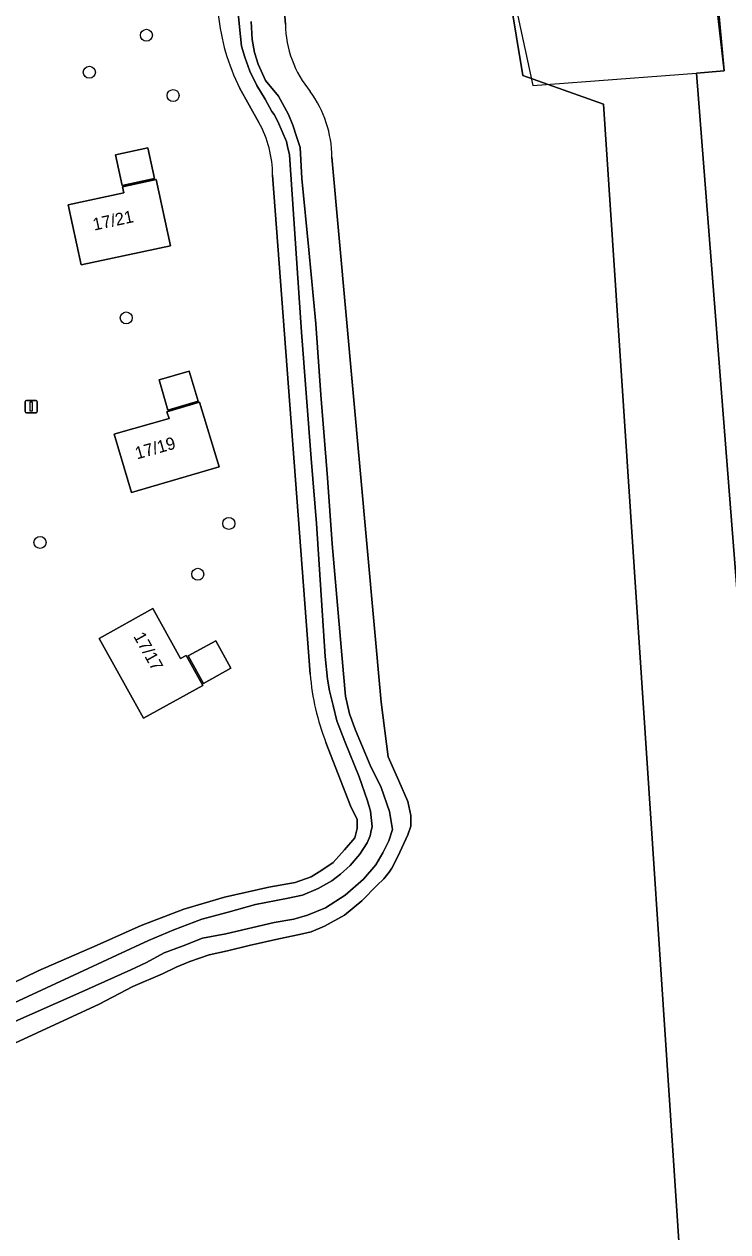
# Model space of a CAD drawing. Extents: x 157793 to 159380, y 380877 to 382313.
# Drawn here: x 157999.2 to 158056.4, y 381071.7 to 381170.1 of the extents above; entities that cross this region are included whole.
import ezdxf

# ---------------------------------------------------------------- set-up
doc = ezdxf.new("R2010")
doc.units = 0
for name, color, linetype in [('IMGEO_Boom', 7, 'Continuous'), ('IMGEO_Erf', 7, 'Continuous'), ('IMGEO_Groenvoorziening', 7, 'Continuous'), ('IMGEO_Hek', 7, 'Continuous'), ('IMGEO_Lichtmast', 7, 'Continuous'), ('IMGEO_Oever', 7, 'Continuous'), ('IMGEO_Pand', 7, 'Continuous'), ('IMGEO_Pand_nummerreeks', 7, 'Continuous'), ('IMGEO_Waterloop', 7, 'Continuous')]:
    doc.layers.add(name, color=color, linetype=linetype)

msp = doc.modelspace()

# ---------------------------------------------------------------- linework, layer by layer
at = {"layer": 'IMGEO_Boom'}
for centre in [(158009.132, 381169.157), (158004.492, 381166.14), (158011.308, 381164.25), (158007.497, 381146.143), (158015.843, 381129.408), (158000.478, 381127.86), (158013.314, 381125.266)]:
    msp.add_circle(centre, 0.489, dxfattribs=at)
at = {"layer": 'IMGEO_Erf'}
msp.add_lwpolyline([(158099.611, 381217.247), (158052.783, 381213.5), (158050.314, 381213.946), (158050.517, 381211.312), (158052.682, 381183.227), (158054.909, 381179.836), (158056.161, 381166.26), (158053.899, 381166.074), (158054.334, 381160.498), (158058.211, 381110.918)], dxfattribs=at)
at = {"layer": 'IMGEO_Groenvoorziening'}
for points in [[(158058.211, 381110.918), (158054.334, 381160.498), (158053.899, 381166.074), (158056.161, 381166.26), (158054.909, 381179.836), (158052.682, 381183.227), (158050.517, 381211.312), (158039.034, 381210.37), (158038.773, 381213.455), (158034.585, 381213.111), (158034.869, 381210.038), (158027.452, 381209.42), (158028.11, 381199.967), (158024.833, 381197.293), (158036.947, 381181.933), (158037.709, 381178.388), (158039.767, 381165.888), (158046.317, 381163.549), (158054.886, 381034.528), (158055.954, 381019.408), (158065.175, 380995.891)], [(158065.175, 380995.891), (158055.954, 381019.408), (158054.886, 381034.528), (158046.317, 381163.549), (158039.767, 381165.888), (158037.709, 381178.388), (158035.215, 381178.178), (158019.881, 381197.791), (158019.23, 381206.041), (158018.738, 381212.267), (158021.715, 381212.507), (158027.429, 381212.967)], [(158017.804, 381200.746), (158020.445, 381170.062)], [(157956.666, 381171.336), (157958.091, 381157.039), (157961.056, 381135.277), (157963.956, 381120.521), (157969.049, 381101.066), (157973.397, 381089.261), (157976.609, 381081.434), (158000.338, 381092.983), (158005.131, 381095.063), (158008.705, 381096.66), (158012.185, 381098.006), (158015.477, 381098.987), (158019.105, 381099.794), (158021.236, 381100.178), (158022.534, 381100.639), (158023.403, 381101.169), (158024.341, 381101.792), (158025.261, 381102.828), (158026.085, 381103.81), (158026.273, 381104.572), (158026.275, 381105.306), (158025.756, 381106.409), (158023.749, 381111.568)], [(158018.292, 381162.055), (158016.704, 381164.87)], [(158024.231, 381159.232), (158028.249, 381114.861), (158028.806, 381110.404), (158029.674, 381108.44), (158030.403, 381106.775), (158030.639, 381105.62), (158030.643, 381104.766), (158030.421, 381104.052), (158029.594, 381102.283), (158029.108, 381101.352), (158028.892, 381101.006), (158028.454, 381100.469), (158027.892, 381099.936), (158026.659, 381098.685), (158025.243, 381097.513), (158023.638, 381096.615), (158022.532, 381096.165), (158021.595, 381095.941), (158019.914, 381095.598), (158017.495, 381095.035), (158015.721, 381094.598), (158014.249, 381094.288), (158012.671, 381093.747), (158011.557, 381093.285), (158010.452, 381092.749), (158008.04, 381091.694), (158005.302, 381090.26), (157978.213, 381077.766)], [(158022.465, 381117.132), (158019.404, 381157.762)]]:
    msp.add_lwpolyline(points, dxfattribs=at)
for points in [[(158006.631, 381159.434), (158009.248, 381160.002), (158009.784, 381157.493), (158007.175, 381156.927)], [(158007.31, 381156.325), (158007.199, 381156.817), (158009.94, 381157.412), (158011.096, 381152.014), (158003.83, 381150.459), (158002.782, 381155.356)], [(158012.62, 381141.82), (158013.343, 381139.359), (158010.885, 381138.643), (158010.164, 381141.099)], [(158010.979, 381137.949), (158010.808, 381138.501), (158013.46, 381139.28), (158015.052, 381134.022), (158007.924, 381131.927), (158006.524, 381136.689), (158006.671, 381136.738)], [(158011.915, 381118.409), (158012.372, 381118.662), (158013.72, 381116.225), (158008.892, 381113.551), (158005.292, 381120.05), (158009.663, 381122.472)], [(158014.773, 381119.859), (158016.014, 381117.614), (158013.77, 381116.373), (158012.528, 381118.617)]]:
    msp.add_lwpolyline(points, close=True, dxfattribs=at)
for centre, radius, start, end in [((158032.528, 381172.642), 17.629, 185.77405, 206.15711), ((158029.237, 381170.181), 8.792, 180.7729, 219.65168), ((158015.08, 381159.168), 9.152, 0.39892, 36.17447), ((158010.58, 381157.767), 8.824, 359.96829, 29.0756), ((158041.64, 381118.627), 19.233, 184.45745, 201.53178)]:
    msp.add_arc(centre, radius, start, end, dxfattribs=at)
at = {"layer": 'IMGEO_Hek'}
for points in [[(158037.709, 381178.388), (158040.568, 381165.078), (158053.899, 381166.074)], [(158056.161, 381166.26), (158055.587, 381171.227)], [(158053.899, 381166.074), (158056.161, 381166.26)], [(158058.211, 381110.918), (158054.334, 381160.498), (158053.899, 381166.074)]]:
    msp.add_lwpolyline(points, dxfattribs=at)
at = {"layer": 'IMGEO_Lichtmast'}
for p, q in [((157999.269, 381138.524), (157999.269, 381139.324)), ((157999.269, 381139.324), (157999.269, 381138.524)), ((157999.369, 381139.424), (158000.159, 381139.424)), ((158000.159, 381139.424), (157999.369, 381139.424)), ((158000.259, 381139.324), (158000.259, 381138.524)), ((158000.259, 381138.524), (158000.259, 381139.324)), ((158000.159, 381138.424), (157999.369, 381138.424)), ((157999.369, 381138.424), (158000.159, 381138.424))]:
    msp.add_line(p, q, dxfattribs=at)
msp.add_lwpolyline([(157999.689, 381139.299), (157999.839, 381139.299), (157999.839, 381138.549), (157999.689, 381138.549), (157999.689, 381139.299)], dxfattribs=at)
for centre, start, end in [((157999.369, 381139.324), 90, 180), ((157999.369, 381139.324), 90, 180), ((158000.159, 381139.324), 0, 90), ((158000.159, 381139.324), 360, 90), ((157999.369, 381138.524), 180, 270), ((157999.369, 381138.524), 180, 270), ((158000.159, 381138.524), 270, 0), ((158000.159, 381138.524), 270, 0)]:
    msp.add_arc(centre, 0.1, start, end, dxfattribs=at)
at = {"layer": 'IMGEO_Oever'}
for points in [[(158020.445, 381170.062), (158017.804, 381200.746)], [(157993.433, 381088.104), (158004.407, 381093.16), (158006.716, 381094.266), (158009.315, 381095.446), (158011.367, 381096.313), (158013.644, 381097.193), (158015.795, 381097.763), (158018.016, 381098.394), (158020.528, 381098.858), (158021.831, 381099.148), (158023.11, 381099.682), (158024.236, 381100.305), (158024.918, 381100.863), (158025.723, 381101.562), (158026.501, 381102.478), (158027.109, 381103.412), (158027.346, 381103.979), (158027.429, 381104.402), (158027.496, 381104.708), (158027.359, 381105.986), (158027.127, 381106.831), (158026.457, 381108.777), (158025.282, 381111.66), (158024.643, 381113.345), (158024.321, 381114.573), (158024.037, 381115.775), (158023.871, 381116.733), (158023.689, 381118.57), (158022.986, 381129.399), (158022.539, 381134.705), (158021.765, 381144.973), (158020.844, 381158.618), (158020.787, 381159.431), (158020.611, 381160.101), (158020.547, 381160.494), (158019.818, 381162.127), (158019.522, 381162.709), (158019.342, 381162.956), (158018.808, 381163.947), (158018.121, 381165.072), (158017.543, 381166.235), (158017.153, 381167.365), (158016.872, 381168.263), (158016.705, 381169.852), (158016.044, 381176.875)], [(158017.65, 381170.266), (158017.734, 381168.814), (158017.935, 381167.763), (158018.242, 381166.799), (158018.832, 381165.468), (158019.891, 381164.206), (158020.688, 381162.718), (158021.054, 381161.824), (158021.384, 381160.844), (158021.653, 381160.006), (158021.781, 381157.505), (158022.349, 381151.689), (158022.926, 381145.664), (158023.318, 381139.893), (158023.869, 381133.121), (158024.24, 381127.735), (158024.691, 381122.754), (158025.173, 381117.167), (158025.339, 381115.351), (158025.659, 381113.919), (158026.153, 381112.588), (158027.342, 381109.73), (158028.232, 381107.905), (158028.922, 381105.953), (158029.16, 381104.48), (158028.858, 381103.564), (158028.363, 381102.587), (158027.805, 381101.62), (158026.789, 381100.44), (158025.3, 381099.15), (158023.707, 381098.11), (158022.254, 381097.512), (158021.131, 381097.175), (158019.544, 381096.919), (158015.588, 381095.993), (158013.693, 381095.632), (158012.115, 381095.007), (158010.585, 381094.45), (158009.136, 381093.671), (158007.873, 381093.055), (158003.624, 381091.17), (157994.367, 381087.051)], [(158016.704, 381164.87), (158018.292, 381162.055)], [(157978.213, 381077.766), (158005.302, 381090.26), (158008.04, 381091.694), (158010.452, 381092.749), (158011.557, 381093.285), (158012.671, 381093.747), (158014.249, 381094.288), (158015.721, 381094.598), (158017.495, 381095.035), (158019.914, 381095.598), (158021.595, 381095.941), (158022.532, 381096.165), (158023.638, 381096.615), (158025.243, 381097.513), (158026.659, 381098.685), (158027.892, 381099.936), (158028.454, 381100.469), (158028.892, 381101.006), (158029.108, 381101.352), (158029.594, 381102.283), (158030.421, 381104.052), (158030.643, 381104.766), (158030.639, 381105.62), (158030.403, 381106.775), (158029.674, 381108.44), (158028.806, 381110.404), (158028.249, 381114.861), (158024.231, 381159.232)], [(158019.404, 381157.762), (158022.465, 381117.132)], [(158023.749, 381111.568), (158025.756, 381106.409), (158026.275, 381105.306), (158026.273, 381104.572), (158026.085, 381103.81), (158025.261, 381102.828), (158024.341, 381101.792), (158023.403, 381101.169), (158022.534, 381100.639), (158021.236, 381100.178), (158019.105, 381099.794), (158015.477, 381098.987), (158012.185, 381098.006), (158008.705, 381096.66), (158005.131, 381095.063), (158000.338, 381092.983), (157976.609, 381081.434)]]:
    msp.add_lwpolyline(points, dxfattribs=at)
for centre, radius, start, end in [((158032.528, 381172.642), 17.629, 185.77405, 206.15711), ((158029.237, 381170.181), 8.792, 180.7729, 219.65168), ((158015.08, 381159.168), 9.152, 0.39892, 36.17447), ((158010.58, 381157.767), 8.824, 359.96829, 29.0756), ((158041.64, 381118.627), 19.233, 184.45745, 201.53178)]:
    msp.add_arc(centre, radius, start, end, dxfattribs=at)
at = {"layer": 'IMGEO_Pand'}
for points in [[(158007.175, 381156.927), (158009.784, 381157.493), (158009.248, 381160.002), (158006.631, 381159.434)], [(158009.94, 381157.412), (158007.199, 381156.817), (158007.31, 381156.325), (158002.782, 381155.356), (158003.83, 381150.459), (158011.096, 381152.014)], [(158010.885, 381138.643), (158013.343, 381139.359), (158012.62, 381141.82), (158010.164, 381141.099)], [(158013.46, 381139.28), (158010.808, 381138.501), (158010.979, 381137.949), (158006.671, 381136.738), (158006.524, 381136.689), (158007.924, 381131.927), (158015.052, 381134.022)], [(158009.663, 381122.472), (158005.292, 381120.05), (158008.892, 381113.551), (158013.72, 381116.225), (158012.372, 381118.662), (158011.915, 381118.409)], [(158012.528, 381118.617), (158013.77, 381116.373), (158016.014, 381117.614), (158014.773, 381119.859)]]:
    msp.add_lwpolyline(points, close=True, dxfattribs=at)
at = {"layer": 'IMGEO_Waterloop'}
for points in [[(158016.044, 381176.875), (158016.705, 381169.852), (158016.872, 381168.263), (158017.153, 381167.365), (158017.543, 381166.235), (158018.121, 381165.072), (158018.808, 381163.947), (158019.342, 381162.956), (158019.522, 381162.709), (158019.818, 381162.127), (158020.547, 381160.494), (158020.611, 381160.101), (158020.787, 381159.431), (158020.844, 381158.618), (158021.765, 381144.973), (158022.539, 381134.705), (158022.986, 381129.399), (158023.689, 381118.57), (158023.871, 381116.733), (158024.037, 381115.775), (158024.321, 381114.573), (158024.643, 381113.345), (158025.282, 381111.66), (158026.457, 381108.777), (158027.127, 381106.831), (158027.359, 381105.986), (158027.496, 381104.708), (158027.429, 381104.402), (158027.346, 381103.979), (158027.109, 381103.412), (158026.501, 381102.478), (158025.723, 381101.562), (158024.918, 381100.863), (158024.236, 381100.305), (158023.11, 381099.682), (158021.831, 381099.148), (158020.528, 381098.858), (158018.016, 381098.394), (158015.795, 381097.763), (158013.644, 381097.193), (158011.367, 381096.313), (158009.315, 381095.446), (158006.716, 381094.266), (158004.407, 381093.16), (157993.433, 381088.104)], [(157994.367, 381087.051), (158003.624, 381091.17), (158007.873, 381093.055), (158009.136, 381093.671), (158010.585, 381094.45), (158012.115, 381095.007), (158013.693, 381095.632), (158015.588, 381095.993), (158019.544, 381096.919), (158021.131, 381097.175), (158022.254, 381097.512), (158023.707, 381098.11), (158025.3, 381099.15), (158026.789, 381100.44), (158027.805, 381101.62), (158028.363, 381102.587), (158028.858, 381103.564), (158029.16, 381104.48), (158028.922, 381105.953), (158028.232, 381107.905), (158027.342, 381109.73), (158026.153, 381112.588), (158025.659, 381113.919), (158025.339, 381115.351), (158025.173, 381117.167), (158024.691, 381122.754), (158024.24, 381127.735), (158023.869, 381133.121), (158023.318, 381139.893), (158022.926, 381145.664), (158022.349, 381151.689), (158021.781, 381157.505), (158021.653, 381160.006), (158021.384, 381160.844), (158021.054, 381161.824), (158020.688, 381162.718), (158019.891, 381164.206), (158018.832, 381165.468), (158018.242, 381166.799), (158017.935, 381167.763), (158017.734, 381168.814), (158017.65, 381170.266)]]:
    msp.add_lwpolyline(points, dxfattribs=at)

# ---------------------------------------------------------------- texts
at = {"layer": 'IMGEO_Pand_nummerreeks'}
for s, rotation, p in [('17/21', 12.07795, (158004.887, 381153.25)), ('17/19', 15.69904, (158008.37, 381134.618)), ('17/17', 298.99718, (158008.05, 381120.226))]:
    msp.add_text(s, height=1, rotation=rotation, dxfattribs=at).set_placement(p)

doc.saveas('drawing.dxf')
